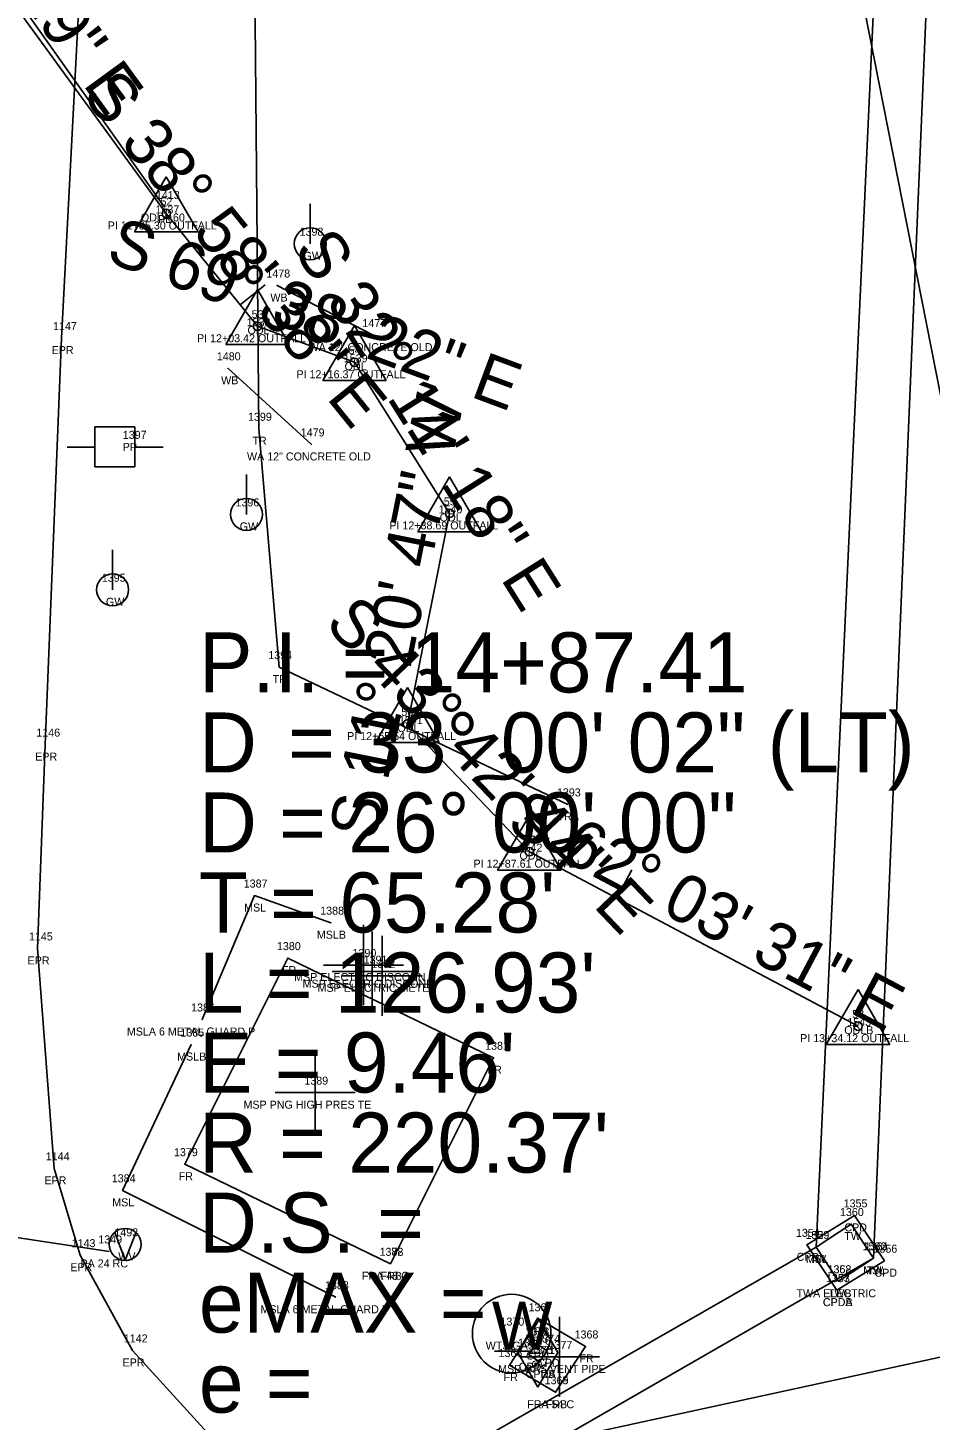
# Model space of a CAD drawing. Extents: x 1812340 to 1815011, y 1177659 to 1180159.
# Drawn here: x 1813680.6 to 1813793.4, y 1178765.1 to 1178939 of the extents above; entities that cross this region are included whole.
import ezdxf

# ---------------------------------------------------------------- set-up
doc = ezdxf.new("R2010")
doc.units = 0
for name, color, linetype in [('RD_EX_BldgApp', 7, 'Continuous'), ('RD_EX_BldgApp_txCode', 7, 'Continuous'), ('RD_EX_Conc', 7, 'Continuous'), ('RD_EX_Conc_txCode', 7, 'Continuous'), ('RD_EX_DR_Pipe', 7, 'Continuous'), ('RD_EX_DR_Pipe_txCode', 7, 'Continuous'), ('RD_EX_Fence_Other', 7, 'Continuous'), ('RD_EX_Fence_Other_txCode', 7, 'Continuous'), ('RD_EX_H2O', 7, 'Continuous'), ('RD_EX_H2O_txCode', 7, 'Continuous'), ('RD_EX_Misc', 7, 'Continuous'), ('RD_EX_Misc_txCode', 7, 'Continuous'), ('RD_EX_Road', 7, 'Continuous'), ('RD_EX_Road_txCode', 7, 'Continuous'), ('RD_EX_UT', 7, 'Continuous'), ('RD_EX_UT_txCode', 7, 'Continuous'), ('RD_EX_VEG', 7, 'Continuous'), ('RD_EX_VEG_txCode', 7, 'Continuous'), ('RD_HC_CL', 7, 'Continuous'), ('RD_HC_Data', 7, 'Continuous'), ('RD_HC_Data_Tic', 7, 'Continuous'), ('RD_HC_txCode', 7, 'Continuous'), ('RD_SMD_Locator', 7, 'Continuous')]:
    doc.layers.add(name, color=color, linetype=linetype)

msp = doc.modelspace()

# ---------------------------------------------------------------- linework, layer by layer
at = {"layer": 'RD_EX_BldgApp'}
for p, q in [((1813723.78, 1178900.65), (1813711.77, 1178906.85)), ((1813716.08, 1178886.99), (1813705.63, 1178896.5))]:
    msp.add_line(p, q, dxfattribs=at)
at = {"layer": 'RD_EX_Conc'}
for points in [[(1813781.73, 1178781.31), (1813777.98, 1178786.97), (1813783.94, 1178790.65), (1813787.7, 1178784.99), (1813781.73, 1178781.31)], [(1813744.59, 1178772.35), (1813743.23, 1178773.25), (1813744.16, 1178774.64), (1813745.52, 1178773.74), (1813744.59, 1178772.35)]]:
    msp.add_lwpolyline(points, dxfattribs=at)
at = {"layer": 'RD_EX_DR_Pipe'}
for p, q in [((1813650.55, 1178983.27), (1813697.68, 1178916.66)), ((1813690.77, 1178786.15), (1813637.71, 1178794.06))]:
    msp.add_line(p, q, dxfattribs=at)
at = {"layer": 'RD_EX_Fence_Other'}
for points in [[(1813725.93, 1178784.6), (1813700.22, 1178797.05), (1813713.13, 1178822.8), (1813738.84, 1178810.35), (1813725.93, 1178784.6)], [(1813746.59, 1178768.55), (1813740.84, 1178771.95), (1813744.58, 1178777.67), (1813750.33, 1178774.27), (1813746.59, 1178768.55)]]:
    msp.add_lwpolyline(points, dxfattribs=at)
at = {"layer": 'RD_EX_H2O'}
msp.add_lwpolyline([(1813697.92, 1178915.85), (1813709.32, 1178901.76), (1813721.45, 1178897.26), (1813733.34, 1178878.37), (1813728.06, 1178852.05), (1813743.31, 1178836.1), (1813784.4, 1178814.3)], dxfattribs=at)
at = {"layer": 'RD_EX_Misc'}
for p, q in [((1813722.59, 1178816.94), (1813722.59, 1178826.94)), ((1813723.66, 1178816.11), (1813723.66, 1178826.11)), ((1813724.9, 1178815.59), (1813724.9, 1178825.59)), ((1813717.59, 1178821.94), (1813727.59, 1178821.94)), ((1813718.66, 1178821.11), (1813728.66, 1178821.11)), ((1813719.9, 1178820.59), (1813729.9, 1178820.59)), ((1813716.53, 1178800.99), (1813716.53, 1178810.99)), ((1813711.53, 1178805.99), (1813721.53, 1178805.99)), ((1813747.06, 1178767.97), (1813747.06, 1178777.97)), ((1813742.06, 1178772.97), (1813752.06, 1178772.97))]:
    msp.add_line(p, q, dxfattribs=at)
for points in [[(1813405.71, 1178572.74), (1813779.17, 1178786.7), (1813799.35, 1179222.21)], [(1813408.47, 1178567.92), (1813786.33, 1178785.29), (1813804.76, 1179221.83)], [(1813702.39, 1178815.13), (1813708.94, 1178830.62), (1813718.51, 1178827.23)], [(1813719.11, 1178780.42), (1813692.45, 1178793.78), (1813701.04, 1178812)]]:
    msp.add_lwpolyline(points, dxfattribs=at)
at = {"layer": 'RD_EX_Road'}
msp.add_lwpolyline([(1813750.48, 1178727.17), (1813739.94, 1178735.23), (1813706.04, 1178760.25), (1813693.68, 1178773.78), (1813687.15, 1178785.68), (1813683.91, 1178796.53), (1813681.81, 1178824.01), (1813682.76, 1178849.48), (1813684.82, 1178900.28), (1813687.23, 1178946.66), (1813689.58, 1178995.92), (1813691.79, 1179045.45)], dxfattribs=at)
at = {"layer": 'RD_EX_UT'}
for p, q in [((1813715.92, 1178912.07), (1813715.92, 1178917.07)), ((1813693.98, 1178889.2), (1813688.98, 1178889.2)), ((1813688.98, 1178889.2), (1813688.98, 1178884.2)), ((1813693.98, 1178884.2), (1813693.98, 1178889.2)), ((1813685.54, 1178886.64), (1813689.01, 1178886.64)), ((1813693.9, 1178886.64), (1813697.54, 1178886.64)), ((1813688.98, 1178884.2), (1813693.98, 1178884.2)), ((1813707.94, 1178878.25), (1813707.94, 1178883.25)), ((1813691.21, 1178868.83), (1813691.21, 1178873.83)), ((1813692.78, 1178785.04), (1813691.47, 1178788.52)), ((1813692.78, 1178785.04), (1813694.1, 1178788.49)), ((1813741.86, 1178773.5), (1813744.36, 1178777.83)), ((1813744.36, 1178777.83), (1813746.86, 1178773.5)), ((1813738.96, 1178773.67), (1813743.59, 1178773.67)), ((1813741.86, 1178773.5), (1813744.36, 1178769.17)), ((1813744.36, 1178769.17), (1813746.86, 1178773.5))]:
    msp.add_line(p, q, dxfattribs=at)
for points in [[(1813817.45, 1178777.9), (1813754.12, 1179098.9), (1813749.26, 1179176.64)], [(1813781.95, 1178782.42), (1813779.17, 1178786.7), (1813783.55, 1178789.57), (1813786.33, 1178785.29), (1813781.95, 1178782.42)], [(1813817.45, 1178777.9), (1813490.2, 1178706.76), (1813294.33, 1178669.42)]]:
    msp.add_lwpolyline(points, dxfattribs=at)
for centre, radius in [((1813715.92, 1178912.07), 2), ((1813707.94, 1178878.25), 2), ((1813691.21, 1178868.83), 2), ((1813692.78, 1178787.03), 2), ((1813741.09, 1178775.88), 4.91)]:
    msp.add_circle(centre, radius, dxfattribs=at)
at = {"layer": 'RD_EX_VEG'}
msp.add_lwpolyline([(1813748.11, 1178842.01), (1813712.02, 1178859.16), (1813709.48, 1178888.95), (1813708.93, 1178949.18), (1813715.24, 1179043.86)], dxfattribs=at)
at = {"layer": 'RD_HC_CL'}
for p, q in [((1813650.05, 1178981.56), (1813697.92, 1178915.85)), ((1813697.92, 1178915.85), (1813709.32, 1178901.76)), ((1813709.32, 1178901.76), (1813721.45, 1178897.26)), ((1813721.45, 1178897.26), (1813733.34, 1178878.37)), ((1813733.34, 1178878.37), (1813728.06, 1178852.05)), ((1813728.06, 1178852.05), (1813743.31, 1178836.1)), ((1813743.31, 1178836.1), (1813784.4, 1178814.3))]:
    msp.add_line(p, q, dxfattribs=at)
at = {"layer": 'RD_HC_Data'}
for p, q in [((1813693.95, 1178913.56), (1813697.92, 1178920.44)), ((1813697.92, 1178920.44), (1813701.89, 1178913.56)), ((1813693.95, 1178913.56), (1813701.89, 1178913.56)), ((1813705.35, 1178899.47), (1813709.32, 1178906.35)), ((1813709.32, 1178906.35), (1813713.29, 1178899.47)), ((1813717.48, 1178894.97), (1813721.46, 1178901.85)), ((1813721.46, 1178901.85), (1813725.42, 1178894.97)), ((1813705.35, 1178899.47), (1813713.29, 1178899.47)), ((1813717.48, 1178894.97), (1813725.42, 1178894.97)), ((1813729.37, 1178876.08), (1813733.34, 1178882.96)), ((1813733.34, 1178882.96), (1813737.31, 1178876.08)), ((1813729.37, 1178876.08), (1813737.31, 1178876.08)), ((1813724.09, 1178849.75), (1813728.06, 1178856.63)), ((1813728.06, 1178856.63), (1813732.03, 1178849.75)), ((1813724.09, 1178849.75), (1813732.03, 1178849.75)), ((1813739.34, 1178833.8), (1813743.31, 1178840.68)), ((1813743.31, 1178840.68), (1813747.28, 1178833.8)), ((1813739.34, 1178833.8), (1813747.28, 1178833.8)), ((1813780.43, 1178812.01), (1813784.4, 1178818.89)), ((1813784.4, 1178818.89), (1813788.37, 1178812.01)), ((1813780.43, 1178812.01), (1813788.37, 1178812.01))]:
    msp.add_line(p, q, dxfattribs=at)
for centre in [(1813697.92, 1178915.85), (1813709.32, 1178901.76), (1813721.45, 1178897.26), (1813733.34, 1178878.37), (1813728.06, 1178852.05), (1813743.31, 1178836.1), (1813784.4, 1178814.3)]:
    msp.add_circle(centre, 0.529, dxfattribs=at)
at = {"layer": 'RD_HC_Data_Tic'}
for p, q in [((1813707.16, 1178904.43), (1813710.27, 1178906.94)), ((1813754.26, 1178830.29), (1813756.13, 1178833.82))]:
    msp.add_line(p, q, dxfattribs=at)
at = {"layer": 'RD_SMD_Locator'}
for centre in [(1813697.68, 1178916.66), (1813697.92, 1178915.85), (1813697.92, 1178915.85), (1813711.77, 1178906.85), (1813709.32, 1178901.76), (1813709.32, 1178901.76), (1813684.82, 1178900.28), (1813723.78, 1178900.65), (1813705.63, 1178896.5), (1813721.45, 1178897.26), (1813721.45, 1178897.26), (1813709.48, 1178888.95), (1813716.08, 1178886.99), (1813733.34, 1178878.37), (1813733.34, 1178878.37), (1813712.02, 1178859.16), (1813728.06, 1178852.05), (1813728.06, 1178852.05), (1813682.76, 1178849.48), (1813748.11, 1178842.01), (1813743.31, 1178836.1), (1813743.31, 1178836.1), (1813708.94, 1178830.62), (1813718.51, 1178827.23), (1813681.81, 1178824.01), (1813713.13, 1178822.8), (1813702.39, 1178815.13), (1813784.4, 1178814.3), (1813784.4, 1178814.3), (1813701.04, 1178812), (1813738.84, 1178810.35), (1813683.91, 1178796.53), (1813700.22, 1178797.05), (1813692.45, 1178793.78), (1813783.55, 1178789.57), (1813783.94, 1178790.65), (1813690.77, 1178786.15), (1813777.98, 1178786.97), (1813779.17, 1178786.7), (1813779.17, 1178786.7), (1813687.15, 1178785.68), (1813725.93, 1178784.6), (1813725.93, 1178784.6), (1813786.33, 1178785.29), (1813786.33, 1178785.29), (1813787.7, 1178784.99), (1813781.73, 1178781.31), (1813781.73, 1178781.31), (1813781.95, 1178782.42), (1813781.95, 1178782.42), (1813719.11, 1178780.42), (1813744.58, 1178777.67), (1813744.16, 1178774.64), (1813750.33, 1178774.27), (1813693.68, 1178773.78), (1813743.23, 1178773.25), (1813744.59, 1178772.35), (1813744.59, 1178772.35), (1813745.52, 1178773.74), (1813740.84, 1178771.95), (1813746.59, 1178768.55), (1813746.59, 1178768.55)]:
    msp.add_circle(centre, 0.001, dxfattribs=at)

# ---------------------------------------------------------------- texts
at = {"layer": 'RD_EX_BldgApp_txCode'}
for s, p in [('1478', (1813710.43, 1178907.85)), ('WB', (1813710.93, 1178904.85)), ('1477', (1813722.43, 1178901.65)), ('WA 12" CONCRETE OLD', (1813715.71, 1178898.65)), ('1480', (1813704.24, 1178897.5)), ('WB', (1813704.78, 1178894.5)), ('1479', (1813714.73, 1178887.99)), ('WA 12" CONCRETE OLD', (1813708.01, 1178884.99))]:
    msp.add_text(s, height=1, dxfattribs=at).set_placement(p)
at = {"layer": 'RD_EX_Conc_txCode'}
for s, p in [('1355', (1813782.6, 1178791.65)), ('CPD', (1813782.69, 1178788.65)), ('1354', (1813776.63, 1178787.97)), ('1356', (1813786.33, 1178785.99)), ('CPD', (1813776.72, 1178784.97)), ('1353', (1813780.39, 1178782.31)), ('1357', (1813780.39, 1178782.31)), ('CPD', (1813786.45, 1178782.99)), ('CPDA', (1813779.99, 1178779.31)), ('CPDB', (1813780.01, 1178779.31)), ('1373', (1813742.82, 1178775.64)), ('1374', (1813744.18, 1178774.74)), ('1372', (1813741.89, 1178774.25)), ('1375', (1813743.25, 1178773.35)), ('1371', (1813743.53, 1178773.35)), ('CPD', (1813741.98, 1178771.25)), ('CPD', (1813742.91, 1178772.64)), ('CPD', (1813744.27, 1178771.74)), ('CPDA', (1813742.85, 1178770.35)), ('CPDB', (1813742.87, 1178770.35))]:
    msp.add_text(s, height=1, dxfattribs=at).set_placement(p)
at = {"layer": 'RD_EX_DR_Pipe_txCode'}
for s, p in [('1413', (1813696.62, 1178917.66)), ('PB', (1813696.9, 1178914.66)), ('1349', (1813689.42, 1178787.15)), ('PA 24 RC', (1813687.19, 1178784.15))]:
    msp.add_text(s, height=1, dxfattribs=at).set_placement(p)
at = {"layer": 'RD_EX_Fence_Other_txCode'}
for s, p in [('1380', (1813711.75, 1178823.8)), ('FR', (1813712.38, 1178820.8)), ('1381', (1813737.78, 1178811.35)), ('FR', (1813738.08, 1178808.35)), ('1379', (1813698.88, 1178798.05)), ('FR', (1813699.47, 1178795.05)), ('1378', (1813724.58, 1178785.6)), ('1382', (1813724.58, 1178785.6)), ('FRA 48 C', (1813722.38, 1178782.6)), ('FRB', (1813724.7, 1178782.6)), ('1367', (1813743.21, 1178778.67)), ('FR', (1813743.82, 1178775.67)), ('1368', (1813748.96, 1178775.27)), ('1366', (1813739.45, 1178772.95)), ('FR', (1813749.57, 1178772.27)), ('FR', (1813740.09, 1178769.95)), ('1365', (1813745.22, 1178769.55)), ('1369', (1813745.22, 1178769.55)), ('FRA 54 C', (1813743.04, 1178766.55)), ('FRB', (1813745.36, 1178766.55))]:
    msp.add_text(s, height=1, dxfattribs=at).set_placement(p)
at = {"layer": 'RD_EX_H2O_txCode'}
for s, p in [('1537', (1813696.57, 1178915.85)), ('ODLA 60', (1813694.74, 1178914.85)), ('1538', (1813707.97, 1178901.76)), ('ODL', (1813708.07, 1178900.76)), ('1539', (1813720.11, 1178897.26)), ('ODL', (1813720.21, 1178896.26)), ('1540', (1813731.96, 1178878.37)), ('ODL', (1813732.1, 1178877.37)), ('1541', (1813727, 1178852.05)), ('ODL', (1813726.82, 1178851.05)), ('1542', (1813741.96, 1178836.1)), ('ODL', (1813742.07, 1178835.1)), ('ODLB', (1813782.68, 1178813.3)), ('1543', (1813783.05, 1178814.3))]:
    msp.add_text(s, height=1, dxfattribs=at).set_placement(p)
at = {"layer": 'RD_EX_Misc_txCode'}
for s, p in [('1387', (1813707.6, 1178831.62)), ('MSL', (1813707.65, 1178828.62)), ('1388', (1813717.16, 1178828.23)), ('MSLB', (1813716.74, 1178825.23)), ('1390', (1813721.2, 1178822.94)), ('1391', (1813722.59, 1178822.11)), ('1392', (1813723.55, 1178821.59)), ('MSP ELECTRIC DISCONN', (1813713.9, 1178819.94)), ('MSP ELECTRIC DISCONN', (1813714.96, 1178819.11)), ('MSP ELECTRIC METER', (1813716.83, 1178818.59)), ('1386', (1813701.02, 1178816.13)), ('MSLA 6 METAL GUARD P', (1813692.99, 1178813.13)), ('1385', (1813699.69, 1178813)), ('MSLB', (1813699.27, 1178810)), ('1389', (1813715.18, 1178806.99)), ('MSP PNG HIGH PRES TE', (1813707.57, 1178803.99)), ('1384', (1813691.1, 1178794.78)), ('MSL', (1813691.16, 1178791.78)), ('1529', (1813777.83, 1178787.7)), ('1532', (1813784.98, 1178786.29)), ('MSL', (1813777.88, 1178784.7)), ('MSL', (1813785.04, 1178783.29)), ('1383', (1813717.76, 1178781.42)), ('MSLA 6 METAL GUARD P', (1813709.7, 1178778.42)), ('1377', (1813745.71, 1178773.97)), ('MSP GAS VENT PIPE', (1813739.4, 1178770.97))]:
    msp.add_text(s, height=1, dxfattribs=at).set_placement(p)
at = {"layer": 'RD_EX_Road_txCode'}
for s, p in [('1147', (1813683.76, 1178901.28)), ('EPR', (1813683.59, 1178898.28)), ('1146', (1813681.67, 1178850.48)), ('EPR', (1813681.53, 1178847.48)), ('1145', (1813680.75, 1178825.01)), ('EPR', (1813680.58, 1178822.01)), ('1144', (1813682.85, 1178797.53)), ('EPR', (1813682.68, 1178794.53)), ('1143', (1813686.09, 1178786.68)), ('EPR', (1813685.92, 1178783.68)), ('1142', (1813692.61, 1178774.78)), ('EPR', (1813692.45, 1178771.78))]:
    msp.add_text(s, height=1, dxfattribs=at).set_placement(p)
at = {"layer": 'RD_EX_UT'}
msp.add_text('W', height=6, dxfattribs=at).set_placement((1813738.62, 1178773.88))
at = {"layer": 'RD_EX_UT_txCode'}
for s, p in [('1398', (1813714.58, 1178913.07)), ('GW', (1813715.08, 1178910.07)), ('1397', (1813692.48, 1178887.69)), ('PP', (1813692.48, 1178886.19)), ('1396', (1813706.57, 1178879.25)), ('GW', (1813707.1, 1178876.25)), ('1395', (1813689.86, 1178869.83)), ('GW', (1813690.37, 1178866.83)), ('1360', (1813782.14, 1178790.57)), ('1493', (1813691.43, 1178788.03)), ('1359', (1813777.83, 1178787.7)), ('TW', (1813782.69, 1178787.57)), ('WV', (1813691.92, 1178785.03)), ('1361', (1813785.24, 1178786.29)), ('TW', (1813778.32, 1178784.7)), ('1362', (1813780.58, 1178783.42)), ('1358', (1813780.6, 1178783.42)), ('TW', (1813785.47, 1178783.29)), ('TWA ELECTRIC', (1813776.7, 1178780.42)), ('TWB', (1813780.62, 1178780.42)), ('1370', (1813739.7, 1178776.88)), ('WTS GAS', (1813737.85, 1178773.88)), ('1376', (1813742.99, 1178774.5)), ('GV', (1813743.57, 1178771.5))]:
    msp.add_text(s, height=1, dxfattribs=at).set_placement(p)
at = {"layer": 'RD_EX_VEG_txCode'}
for s, p in [('1399', (1813708.14, 1178889.95)), ('TR', (1813708.69, 1178886.95)), ('1394', (1813710.67, 1178860.16)), ('TR', (1813711.22, 1178857.16)), ('1393', (1813746.76, 1178843.01)), ('TRA', (1813746.83, 1178840.01))]:
    msp.add_text(s, height=1, dxfattribs=at).set_placement(p)
at = {"layer": 'RD_HC_Data'}
for s, rotation, p in [('S 36%%d 04\' 29" E', 306.0747, (1813658.75, 1178971.31)), ('S 38%%d 58\' 38" E', 308.9771, (1813687.26, 1178930.61)), ('S 69%%d 38\' 22" E', 339.6395, (1813690.19, 1178909.93)), ('S 32%%d 11\' 18" E', 302.1883, (1813713.73, 1178911.4)), ('S 11%%d 20\' 47" W', 78.6536, (1813724.1, 1178837.38)), ('S 43%%d 42\' 44" E', 313.7122, (1813717.58, 1178864.45)), ('S 62%%d 03\' 31" E', 332.0585, (1813740.26, 1178838.85))]:
    msp.add_text(s, height=6, rotation=rotation, dxfattribs=at).set_placement(p)
for s, p in [('P.I. = 14+87.41', (1813702, 1178856)), ('    = 33%%d 00\' 02" (LT)', (1813702, 1178846)), ('D', (1813702, 1178846)), ('D = 26%%d 00\' 00"', (1813702, 1178836)), ("T = 65.28'", (1813702, 1178826)), ("L = 126.93'", (1813702, 1178816)), ("E = 9.46'", (1813702, 1178806)), ("R = 220.37'", (1813702, 1178796)), ('D.S. = ', (1813702, 1178786)), ('eMAX = ', (1813702, 1178776)), ('e = ', (1813702, 1178766))]:
    msp.add_text(s, height=7.5, dxfattribs=at).set_placement(p)
at = {"layer": 'RD_HC_txCode'}
for s, p in [('52', (1813697.19, 1178916.85)), ('PI 11+85.30 OUTFALL', (1813690.6, 1178913.85)), ('53', (1813708.59, 1178902.76)), ('PI 12+03.42 OUTFALL', (1813701.76, 1178899.76)), ('54', (1813720.72, 1178898.26)), ('PI 12+16.37 OUTFALL', (1813714.19, 1178895.26)), ('55', (1813732.61, 1178879.37)), ('PI 12+38.69 OUTFALL', (1813725.8, 1178876.37)), ('56', (1813727.3, 1178853.05)), ('PI 12+65.54 OUTFALL', (1813720.52, 1178850.05)), ('57', (1813742.58, 1178837.1)), ('PI 12+87.61 OUTFALL', (1813736.33, 1178834.1)), ('58', (1813783.67, 1178815.3)), ('PI 13+34.12 OUTFALL', (1813777.16, 1178812.3))]:
    msp.add_text(s, height=1, dxfattribs=at).set_placement(p)

doc.saveas('drawing.dxf')
